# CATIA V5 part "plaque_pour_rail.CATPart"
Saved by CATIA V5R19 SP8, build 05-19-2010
Part number: plaque_pour_rail
Bounding box of the stored display mesh (mm): x 0 to 3, y -30 to 30, z -100 to -20
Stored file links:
  U:\Thinkmotion\Assemblage final\plaque_pour_rail.CATPart
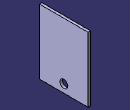
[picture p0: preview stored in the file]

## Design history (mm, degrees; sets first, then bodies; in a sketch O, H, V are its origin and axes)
Body1 (main body)
  Sketch1 on yz-plane, origin (0, 0, 0), H (0, 1, 0), V (0, 0, 1)
    line L1 (-30, -20) -> (30, -20)
    line L2 (30, -20) -> (30, -100)
    line L3 (30, -100) -> (-30, -100)
    line L4 (-30, -100) -> (-30, -20)
    length L1 = 60
    distance V L2 = 30
    length L2 = 80
    distance L1 H = 20
    horizontal: L1 H, L3 H
    vertical: L2 V, L4 V
  Pad1: profile Sketch1, direction (1, 0, 0), length 3
  Sketch2 on end face of Pad1, origin (3, -3.2807, -17.2366), H (0, 1, 0), V (0, 0, 1)
    point P1 (3.2807, -72.7634)
    reference intersected line E1 through (3.2807, 0) direction (0, 1) from zx-plane
    reference projected line E2 (-26.7193, -82.7634) -> (33.2807, -82.7634) from edge [face of Pad1 from Sketch1.L3 | end face of Pad1]
    distance P1 E2 = 10
    coincidence: P1 E1
  Hole1: placed by Sketch2, at (3, 0, -90) direction (-1, 0, 0), diameter 10, depth 10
